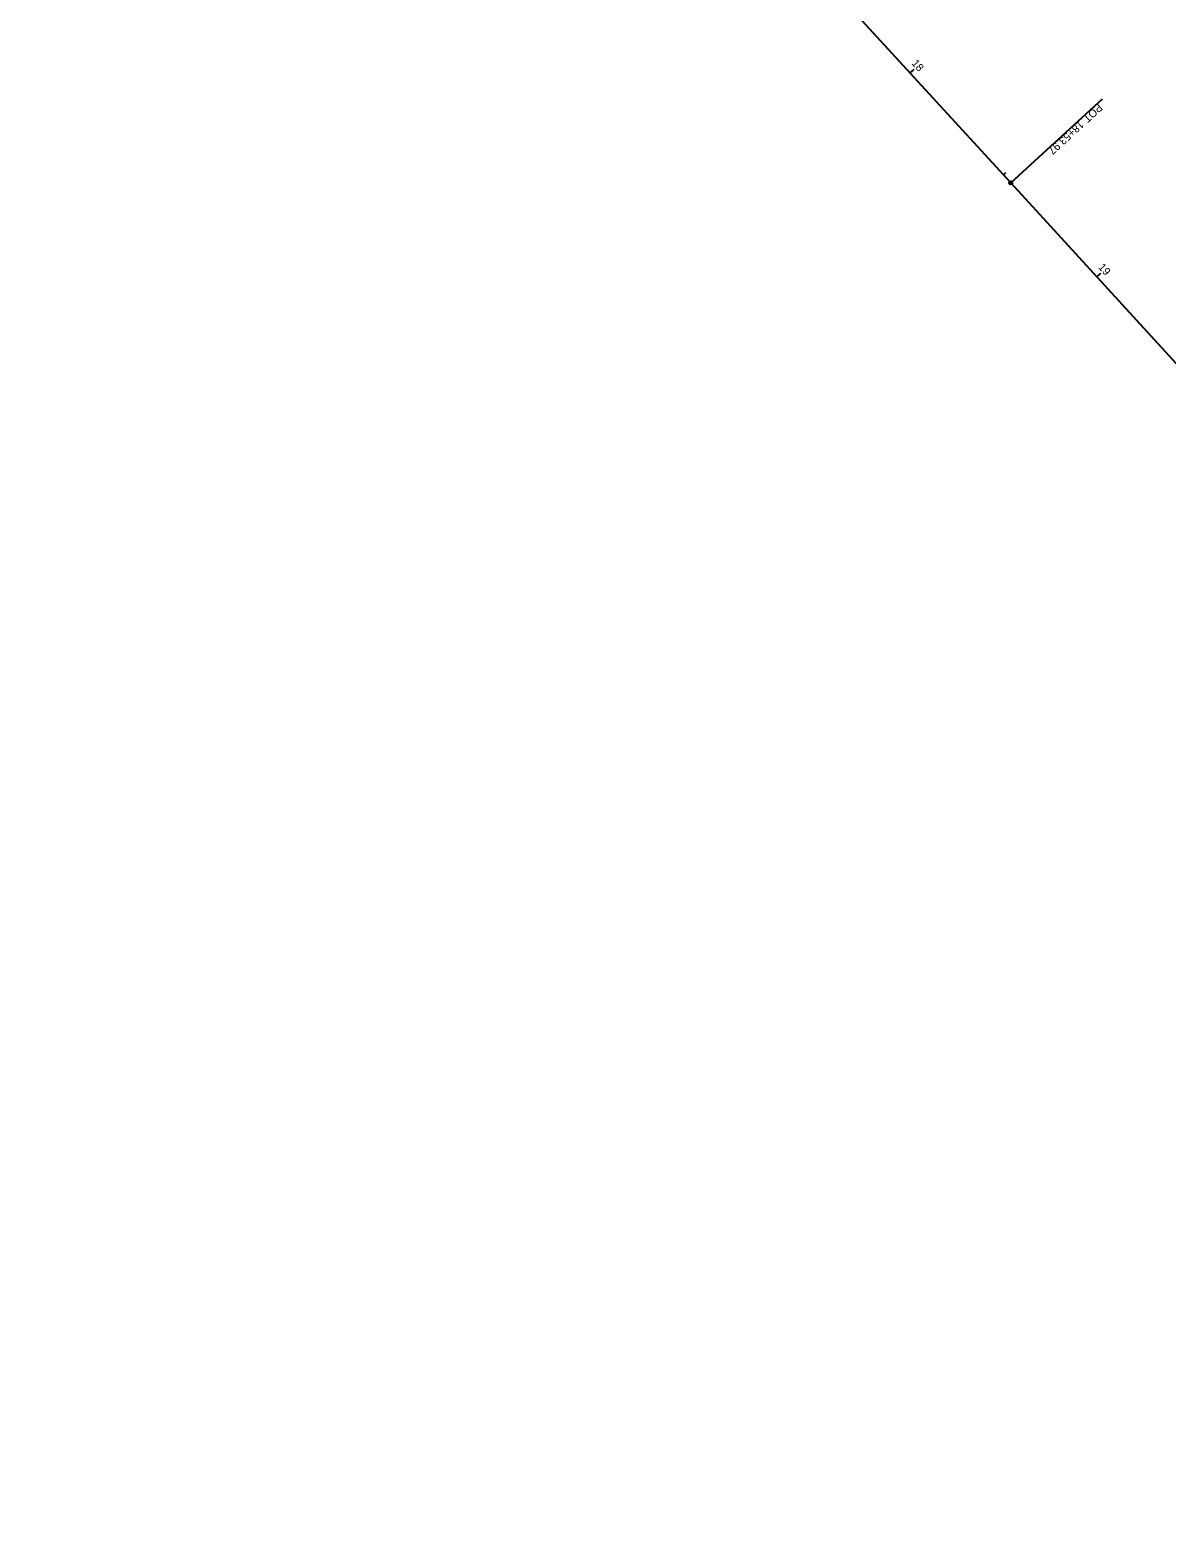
# Model space of a CAD drawing. Extents: x 2196614 to 2198263, y 660890 to 662319.
# Drawn here: x 2197427 to 2197838, y 660891 to 661437 of the extents above; entities that cross this region are included whole.
import ezdxf

# ---------------------------------------------------------------- set-up
doc = ezdxf.new("R2010")
doc.units = 0
for name, color, linetype in [('Default', 7, 'Continuous'), ('GE_X_Alignment', 7, 'Continuous'), ('GE_X_Alignment_1000_Stations', 7, 'Continuous'), ('GE_X_Alignment_100_Stations', 7, 'Continuous'), ('GE_X_Alignment_500_Stations', 7, 'Continuous')]:
    doc.layers.add(name, color=color, linetype=linetype)

msp = doc.modelspace()

# ---------------------------------------------------------------- linework, layer by layer
at = {"layer": 'Default'}
for centre in [(2197744.94, 661421.15), (2197781.39, 661381.34), (2197781.39, 661381.34), (2197781.39, 661381.34), (2197812.47, 661347.39)]:
    msp.add_circle(centre, 0.0000833, dxfattribs=at)
at = {"layer": 'GE_X_Alignment'}
for p, q in [((2197238.07, 661974.69), (2197781.39, 661381.34)), ((2197781.39, 661381.34), (2198230.18, 660891.09))]:
    msp.add_line(p, q, dxfattribs=at)
at = {"layer": 'GE_X_Alignment_1000_Stations'}
msp.add_line((2197781.39, 661381.34), (2197814.58, 661411.73), dxfattribs=at)
msp.add_circle((2197781.39, 661381.34), 0.6, dxfattribs=at)
at = {"layer": 'GE_X_Alignment_100_Stations'}
for p, q in [((2197744.94, 661421.15), (2197746.41, 661422.5)), ((2197781.39, 661381.34), (2197814.58, 661411.73)), ((2197778.71, 661384.27), (2197779.59, 661385.08)), ((2197812.47, 661347.39), (2197813.94, 661348.74))]:
    msp.add_line(p, q, dxfattribs=at)
msp.add_circle((2197781.39, 661381.34), 0.6, dxfattribs=at)
at = {"layer": 'GE_X_Alignment_500_Stations'}
for p, q in [((2197744.94, 661421.15), (2197745.82, 661421.96)), ((2197781.39, 661381.34), (2197814.58, 661411.73)), ((2197812.47, 661347.39), (2197813.35, 661348.2))]:
    msp.add_line(p, q, dxfattribs=at)
msp.add_circle((2197781.39, 661381.34), 0.6, dxfattribs=at)

# ---------------------------------------------------------------- texts
at = {"layer": 'GE_X_Alignment_1000_Stations'}
for s, p in [('POT', (2197813.02, 661410.24)), ('18+53.97', (2197806.29, 661404.08))]:
    msp.add_text(s, height=2.8, rotation=222.4723, dxfattribs=at).set_placement(p)
at = {"layer": 'GE_X_Alignment_100_Stations'}
for s, rotation, p in [('18', 312.4797, (2197745.34, 661424.48)), ('POT', 222.4723, (2197813.02, 661410.24)), ('18+53.97', 222.4723, (2197806.29, 661404.08)), ('19', 312.4723, (2197812.88, 661350.71))]:
    msp.add_text(s, height=2.8, rotation=rotation, dxfattribs=at).set_placement(p)
at = {"layer": 'GE_X_Alignment_500_Stations'}
for s, p in [('POT', (2197813.02, 661410.24)), ('18+53.97', (2197806.29, 661404.08))]:
    msp.add_text(s, height=2.8, rotation=222.4723, dxfattribs=at).set_placement(p)

doc.saveas('drawing.dxf')
